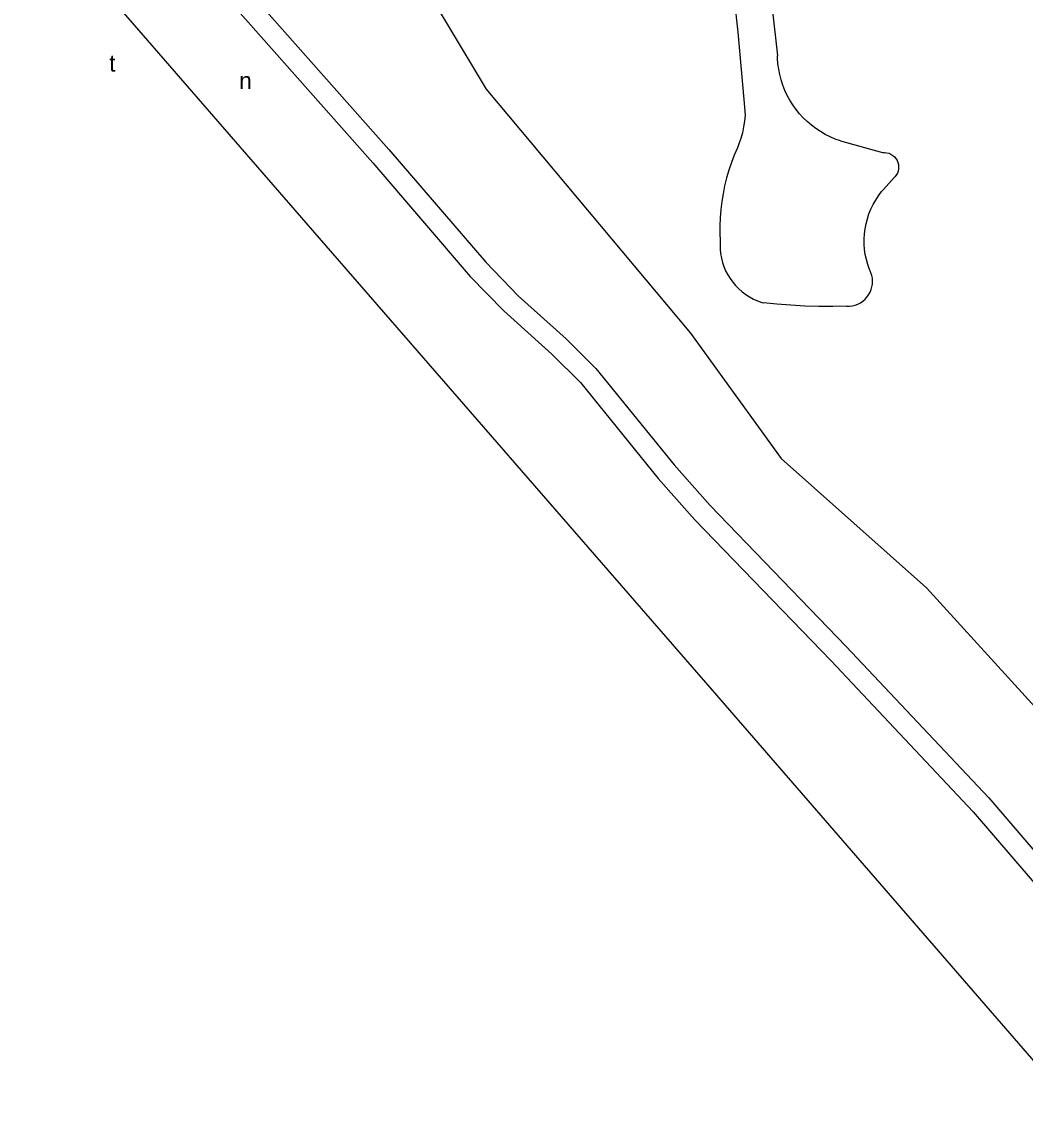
# Model space of a CAD drawing. Extents: x 156066 to 157805, y 383432 to 385631.
# Drawn here: x 157088.7 to 157328.2, y 383897.1 to 384159.6 of the extents above; entities that cross this region are included whole.
import ezdxf

# ---------------------------------------------------------------- set-up
doc = ezdxf.new("R2010")
doc.units = 0
doc.layers.add('BLT_Basislijn', color=7, linetype='Continuous')
doc.layers.add('BLT_Centroide', color=7, linetype='Continuous')

msp = doc.modelspace()

# ---------------------------------------------------------------- linework, layer by layer
at = {"layer": 'BLT_Basislijn'}
for p, q in [((157088.75, 384189.77), (157156.52, 384111.66)), ((157267.82, 384162.92), (157269.11, 384151.56)), ((157284.15, 384131.22), (157294.15, 384128.42)), ((157296.99, 384122.49), (157294.4, 384119.65))]:
    msp.add_line(p, q, dxfattribs=at)
for points in [[(157088.75, 384280.38), (157125.95, 384248.8), (157138.38, 384224.9), (157179.5, 384177.08), (157199.58, 384143.61), (157248.35, 384085.28), (157269.97, 384055.34), (157304.71, 384024.5), (157340.39, 383985.23), (157391.35, 383930.37), (157420.88, 383940.11), (157470.65, 383958.4), (157478.75, 383966.19), (157481.29, 383979.08), (157476.65, 383991.08), (157465.85, 384006.22), (157459.4, 384019.12), (157463.86, 384023.42)], [(157088.75, 384228.89), (157113.01, 384200.77), (157176.31, 384129.21)], [(157088.75, 384221.24), (157109.24, 384197.48), (157172.52, 384125.95)], [(157258.79, 384165.24), (157259.63, 384157.22), (157260.4, 384149.19), (157261.08, 384141.15), (157261.37, 384137.36)], [(157284.15, 384131.22), (157282.91, 384131.67), (157281.7, 384132.19), (157280.52, 384132.78), (157279.38, 384133.44), (157278.28, 384134.17), (157277.23, 384134.97), (157276.22, 384135.83), (157275.27, 384136.75), (157274.38, 384137.72), (157273.55, 384138.75), (157272.79, 384139.82), (157272.09, 384140.94), (157271.46, 384142.1), (157270.9, 384143.29), (157270.41, 384144.52), (157270, 384145.78), (157269.66, 384147.05), (157269.41, 384148.35), (157269.23, 384149.65), (157269.13, 384150.97), (157269.11, 384151.56)], [(157261.37, 384137.36), (157261.24, 384135.96), (157261.02, 384134.56), (157260.73, 384133.18), (157260.36, 384131.83), (157259.91, 384130.49), (157259.57, 384129.61)], [(157176.31, 384129.21), (157199.46, 384102.24), (157207.24, 384094.23), (157218.7, 384083.96), (157225.78, 384076.88), (157244.48, 384053.86), (157253.02, 384044.14), (157285.53, 384010.47)], [(157259.57, 384129.61), (157258.8, 384127.85), (157258.11, 384126.05), (157257.49, 384124.23), (157256.95, 384122.38), (157256.49, 384120.51), (157256.11, 384118.62), (157255.8, 384116.72), (157255.57, 384114.81), (157255.42, 384112.89), (157255.36, 384110.97), (157255.37, 384109.05), (157255.44, 384107.51)], [(157294.15, 384128.42), (157294.67, 384128.45), (157295.2, 384128.39), (157295.71, 384128.26), (157296.19, 384128.05), (157296.64, 384127.77), (157297.03, 384127.43), (157297.38, 384127.03), (157297.65, 384126.58), (157297.86, 384126.1), (157297.99, 384125.59), (157298.04, 384125.06), (157298.02, 384124.54), (157297.91, 384124.02), (157297.73, 384123.53), (157297.47, 384123.07), (157297.15, 384122.65), (157296.99, 384122.49)], [(157172.52, 384125.95), (157195.77, 384098.87), (157203.77, 384090.62), (157215.27, 384080.32), (157222.06, 384073.53), (157240.66, 384050.63), (157249.35, 384040.74), (157281.89, 384007.05)], [(157291.05, 384100.54), (157290.65, 384101.7), (157290.33, 384102.89), (157290.08, 384104.09), (157289.91, 384105.31), (157289.82, 384106.54), (157289.82, 384107.77), (157289.89, 384109), (157290.04, 384110.22), (157290.27, 384111.43), (157290.58, 384112.62), (157290.96, 384113.79), (157291.42, 384114.93), (157291.96, 384116.04), (157292.56, 384117.11), (157293.23, 384118.14), (157293.97, 384119.12), (157294.4, 384119.65)], [(157156.52, 384111.66), (157253.52, 384000), (157342.76, 383897.12)], [(157255.44, 384107.51), (157255.39, 384106.44), (157255.42, 384105.37), (157255.52, 384104.31), (157255.71, 384103.25), (157255.98, 384102.22), (157256.32, 384101.2), (157256.74, 384100.22), (157257.23, 384099.27), (157257.79, 384098.35), (157258.42, 384097.49), (157259.11, 384096.67), (157259.86, 384095.9), (157260.66, 384095.2), (157261.52, 384094.55), (157262.42, 384093.97), (157263.36, 384093.46), (157264.33, 384093.03), (157265.34, 384092.66), (157265.76, 384092.53)], [(157285.63, 384091.76), (157286.32, 384091.77), (157287, 384091.85), (157287.67, 384092.02), (157288.31, 384092.26), (157288.92, 384092.58), (157289.49, 384092.96), (157290.01, 384093.41), (157290.47, 384093.91), (157290.88, 384094.47), (157291.21, 384095.07), (157291.48, 384095.7), (157291.66, 384096.36), (157291.77, 384097.04), (157291.81, 384097.72), (157291.76, 384098.41), (157291.63, 384099.08), (157291.42, 384099.74), (157291.14, 384100.36), (157291.05, 384100.54)], [(157285.63, 384091.76), (157282.29, 384091.69), (157278.95, 384091.7), (157275.61, 384091.79), (157272.28, 384091.97), (157268.95, 384092.22), (157265.76, 384092.53)], [(157285.53, 384010.47), (157319.53, 383974.29), (157348.76, 383940.24), (157366.95, 383918.21)], [(157281.89, 384007.05), (157315.81, 383970.95), (157344.93, 383937.03), (157363.1, 383915.03)]]:
    msp.add_lwpolyline(points, dxfattribs=at)

# ---------------------------------------------------------------- texts
at = {"layer": 'BLT_Centroide'}
for s, p in [('t', (157109.56, 384147.79)), ('n', (157140.62, 384143.63))]:
    msp.add_text(s, height=4, dxfattribs=at).set_placement(p)

doc.saveas('drawing.dxf')
